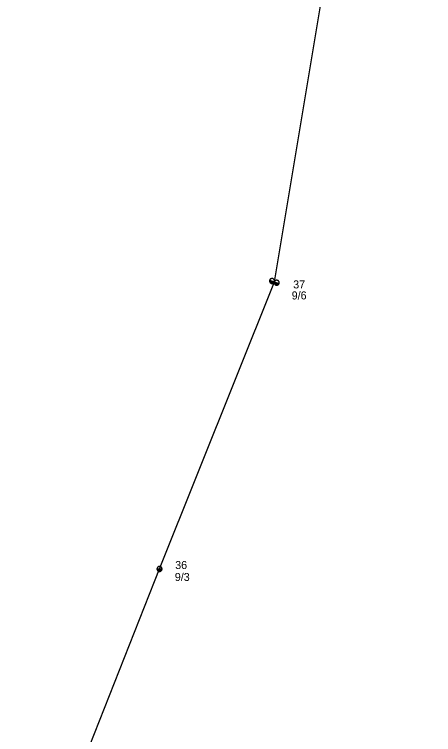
# Model space of a CAD drawing. Extents: x -788458 to -786145, y -1154772 to -1152372.
# Drawn here: x -787370.8 to -787318.5, y -1152907.4 to -1152817.4 of the extents above; entities that cross this region are included whole.
import ezdxf

# ---------------------------------------------------------------- set-up
doc = ezdxf.new("R2010")
doc.units = 0
for name, color, linetype in [('Vrstva 1', 7, 'Continuous'), ('Vrstva 12', 7, 'Continuous'), ('Vrstva 13', 7, 'Continuous'), ('Vrstva 14', 7, 'Continuous'), ('Vrstva 2', 7, 'Continuous')]:
    doc.layers.add(name, color=color, linetype=linetype)

# ---------------------------------------------------------------- blocks, each defined once
blk = doc.blocks.new('NN440')
at = {"layer": 'Vrstva 2'}
for points in [[(0.63, 0), (0.63, 0.06), (0.62, 0.13), (0.6, 0.19), (0.58, 0.25), (0.55, 0.31), (0.51, 0.37), (0.47, 0.42), (0.42, 0.46), (0.37, 0.51), (0.32, 0.54), (0.26, 0.57), (0.2, 0.59), (0.13, 0.61), (0.07, 0.62), (0, 0.63), (-0.06, 0.62), (-0.13, 0.61), (-0.19, 0.59), (-0.26, 0.57), (-0.31, 0.54), (-0.37, 0.51), (-0.42, 0.46), (-0.47, 0.42), (-0.51, 0.37), (-0.54, 0.31), (-0.57, 0.25), (-0.6, 0.19), (-0.62, 0.13), (-0.63, 0.06), (-0.63, 0), (-0.63, -0.07), (-0.62, -0.14), (-0.6, -0.2), (-0.57, -0.26), (-0.54, -0.32), (-0.51, -0.37), (-0.47, -0.43), (-0.42, -0.47), (-0.37, -0.51), (-0.31, -0.55), (-0.26, -0.58), (-0.19, -0.6), (-0.13, -0.62), (-0.06, -0.63), (0, -0.63), (0.07, -0.63), (0.13, -0.62), (0.2, -0.6), (0.26, -0.58), (0.32, -0.55), (0.37, -0.51), (0.42, -0.47), (0.47, -0.43), (0.51, -0.37), (0.55, -0.32), (0.58, -0.26), (0.6, -0.2), (0.62, -0.14), (0.63, -0.07), (0.63, 0)], [(-0.63, 0), (0.63, 0)], [(-0.6, -0.18), (0.57, -0.18)], [(-0.51, -0.32), (0.5, -0.32)], [(-0.37, -0.47), (0.35, -0.47)]]:
    blk.add_lwpolyline(points, dxfattribs=at)
blk = doc.blocks.new('NN450')
at = {"layer": 'Vrstva 2'}
for points in [[(0, 0), (0, 0.07), (-0.01, 0.13), (-0.03, 0.19), (-0.05, 0.25), (-0.08, 0.31), (-0.12, 0.37), (-0.16, 0.42), (-0.21, 0.46), (-0.26, 0.51), (-0.31, 0.54), (-0.37, 0.57), (-0.43, 0.59), (-0.5, 0.61), (-0.56, 0.62), (-0.63, 0.62), (-0.69, 0.62), (-0.75, 0.61), (-0.82, 0.59), (-0.88, 0.57), (-0.94, 0.54), (-0.99, 0.51), (-1.04, 0.46), (-1.09, 0.42), (-1.13, 0.37), (-1.17, 0.31), (-1.2, 0.25), (-1.22, 0.19), (-1.24, 0.13), (-1.25, 0.07), (-1.25, 0), (-1.25, -0.07), (-1.24, -0.13), (-1.22, -0.19), (-1.2, -0.25), (-1.17, -0.31), (-1.13, -0.37), (-1.09, -0.42), (-1.04, -0.46), (-0.99, -0.51), (-0.94, -0.54), (-0.88, -0.57), (-0.82, -0.59), (-0.75, -0.61), (-0.69, -0.62), (-0.62, -0.63), (-0.56, -0.62), (-0.5, -0.61), (-0.43, -0.59), (-0.37, -0.57), (-0.31, -0.54), (-0.26, -0.51), (-0.21, -0.46), (-0.16, -0.42), (-0.12, -0.37), (-0.08, -0.31), (-0.05, -0.25), (-0.03, -0.19), (-0.01, -0.13), (0, -0.07), (0, 0)], [(1.25, 0), (1.25, 0.07), (1.24, 0.13), (1.22, 0.19), (1.2, 0.25), (1.17, 0.31), (1.13, 0.37), (1.09, 0.42), (1.04, 0.46), (0.99, 0.51), (0.94, 0.54), (0.88, 0.57), (0.82, 0.59), (0.75, 0.61), (0.69, 0.62), (0.62, 0.62), (0.56, 0.62), (0.5, 0.61), (0.43, 0.59), (0.37, 0.57), (0.31, 0.54), (0.26, 0.51), (0.21, 0.46), (0.16, 0.42), (0.12, 0.37), (0.08, 0.31), (0.05, 0.25), (0.03, 0.19), (0.01, 0.13), (0, 0.07), (0, 0), (0, -0.07), (0.01, -0.13), (0.03, -0.19), (0.05, -0.25), (0.08, -0.31), (0.12, -0.37), (0.16, -0.42), (0.21, -0.46), (0.26, -0.51), (0.31, -0.54), (0.37, -0.57), (0.43, -0.59), (0.5, -0.61), (0.56, -0.62), (0.63, -0.63), (0.69, -0.62), (0.75, -0.61), (0.82, -0.59), (0.88, -0.57), (0.94, -0.54), (0.99, -0.51), (1.04, -0.46), (1.09, -0.42), (1.13, -0.37), (1.17, -0.31), (1.2, -0.25), (1.22, -0.19), (1.24, -0.13), (1.25, -0.07), (1.25, 0)], [(-1.25, 0), (1.25, 0)], [(-1.23, -0.16), (-0.02, -0.16)], [(-1.16, -0.32), (-0.09, -0.32)], [(-1.03, -0.47), (-0.22, -0.47)], [(0.02, -0.16), (1.23, -0.16)], [(0.09, -0.32), (1.16, -0.32)], [(0.22, -0.47), (1.03, -0.47)]]:
    blk.add_lwpolyline(points, dxfattribs=at)

msp = doc.modelspace()

# ---------------------------------------------------------------- linework, layer by layer
at = {"layer": 'Vrstva 1'}
msp.add_lwpolyline([(-787370.84, -1152932.51), (-787352.71, -1152886.68), (-787338.36, -1152850.84), (-787331.68, -1152810.84), (-787329.05, -1152772.02), (-787318.461, -1152738.272)], dxfattribs=at)

# ---------------------------------------------------------------- block references
at = {"layer": 'Vrstva 13', "xscale": 0.5, "yscale": 0.5, "rotation": -20.22089869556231}
msp.add_blockref('NN450', (-787338.36, -1152850.84), dxfattribs=at)
at = {"layer": 'Vrstva 13', "xscale": 0.5, "yscale": 0.5}
msp.add_blockref('NN440', (-787352.71, -1152886.68), dxfattribs=at)

# ---------------------------------------------------------------- texts
at = {"layer": 'Vrstva 12'}
for s, p in [('9/6', (-787336.191, -1152853.033)), ('9/3', (-787350.795, -1152888.181))]:
    msp.add_text(s, height=1, dxfattribs=at).set_placement(p)
at = {"layer": 'Vrstva 14'}
for s, p in [('37', (-787336.005, -1152851.659)), ('36', (-787350.749, -1152886.69))]:
    msp.add_text(s, height=1, dxfattribs=at).set_placement(p)

doc.saveas('drawing.dxf')
